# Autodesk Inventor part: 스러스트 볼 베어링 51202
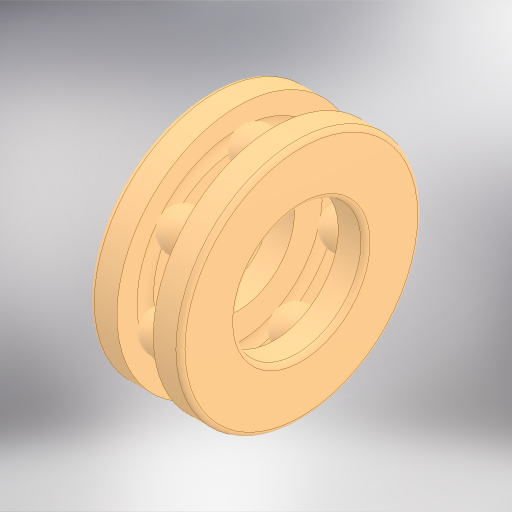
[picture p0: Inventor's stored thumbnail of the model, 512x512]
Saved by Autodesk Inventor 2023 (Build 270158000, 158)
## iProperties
Created: 2026-07
Part Number: 스러스트 볼 베어링 51202
Material: 강철, 연강
Description: 롤링 베어링 - 플랫 뒷면이 있는 스러스트 볼 베어링
Document SubType Name: Modeling
Designer: home
Density: 7.85 g/cm^3
Appearance: 기본값
Author: jhkim
Sending System: Autodesk Inventor 2027
Preprocessor: ST-DEVELOPER v20.1
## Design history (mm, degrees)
feature "Solid1"
feature "Solid1:1"
feature "Solid1:2"
feature "Solid1:3"
feature "Solid1:4"
feature "Solid1:5"
feature "Solid1:6"
feature "Solid1:7"
feature "Solid1:8"
node "솔리드1"
node "솔리드2"
node "솔리드3"
node "솔리드4"
node "솔리드5"
node "솔리드6"
node "솔리드7"
node "솔리드8"
node "솔리드9"
